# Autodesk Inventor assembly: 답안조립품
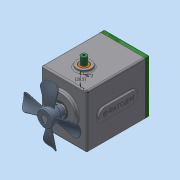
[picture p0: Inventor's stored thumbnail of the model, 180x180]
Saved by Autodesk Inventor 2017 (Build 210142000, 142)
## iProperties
Part Number: 답안조립품
Material: 일반
Document SubType Name: Assembly
Designer: MRC
Author: MRC
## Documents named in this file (17)
- C:\Users\MRC\Desktop\새 폴더 (2)\610205V1001\답안조립품.iam
- C:\Users\MRC\Desktop\새 폴더 (2)\610205V1001\본체.ipt
- C:\Users\MRC\Desktop\새 폴더 (2)\610205V1001\가변스프링.ipt
- C:\Users\MRC\Desktop\새 폴더 (2)\610205V1001\멈춤나사 M3x8.ipt
- C:\Users\MRC\Desktop\새 폴더 (2)\610205V1001\메인 기어 축.ipt
- C:\Users\MRC\Desktop\새 폴더 (2)\610205V1001\베어링 608.ipt
- C:\Users\MRC\Desktop\새 폴더 (2)\610205V1001\베어링 6903.ipt
- C:\Users\MRC\Desktop\새 폴더 (2)\610205V1001\볼트 M4 x 10.ipt
- C:\Users\MRC\Desktop\새 폴더 (2)\610205V1001\부시.ipt
- C:\Users\MRC\Desktop\새 폴더 (2)\610205V1001\서브 기어 축.ipt
- C:\Users\MRC\Desktop\새 폴더 (2)\610205V1001\슬라이더.ipt
- C:\Users\MRC\Desktop\새 폴더 (2)\610205V1001\오일 실 8 22 7.ipt
- C:\Users\MRC\Desktop\새 폴더 (2)\610205V1001\오일 실 17 30 8.ipt
- C:\Users\MRC\Desktop\새 폴더 (2)\610205V1001\커버.ipt
- C:\Users\MRC\Desktop\새 폴더 (2)\610205V1001\키 5 x 5 x 24.ipt
- C:\Users\MRC\Desktop\새 폴더 (2)\610205V1001\팬날개.ipt
- 팬날개.ipt
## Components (1 placed, 1 different names)
1. 가변스프링:1
